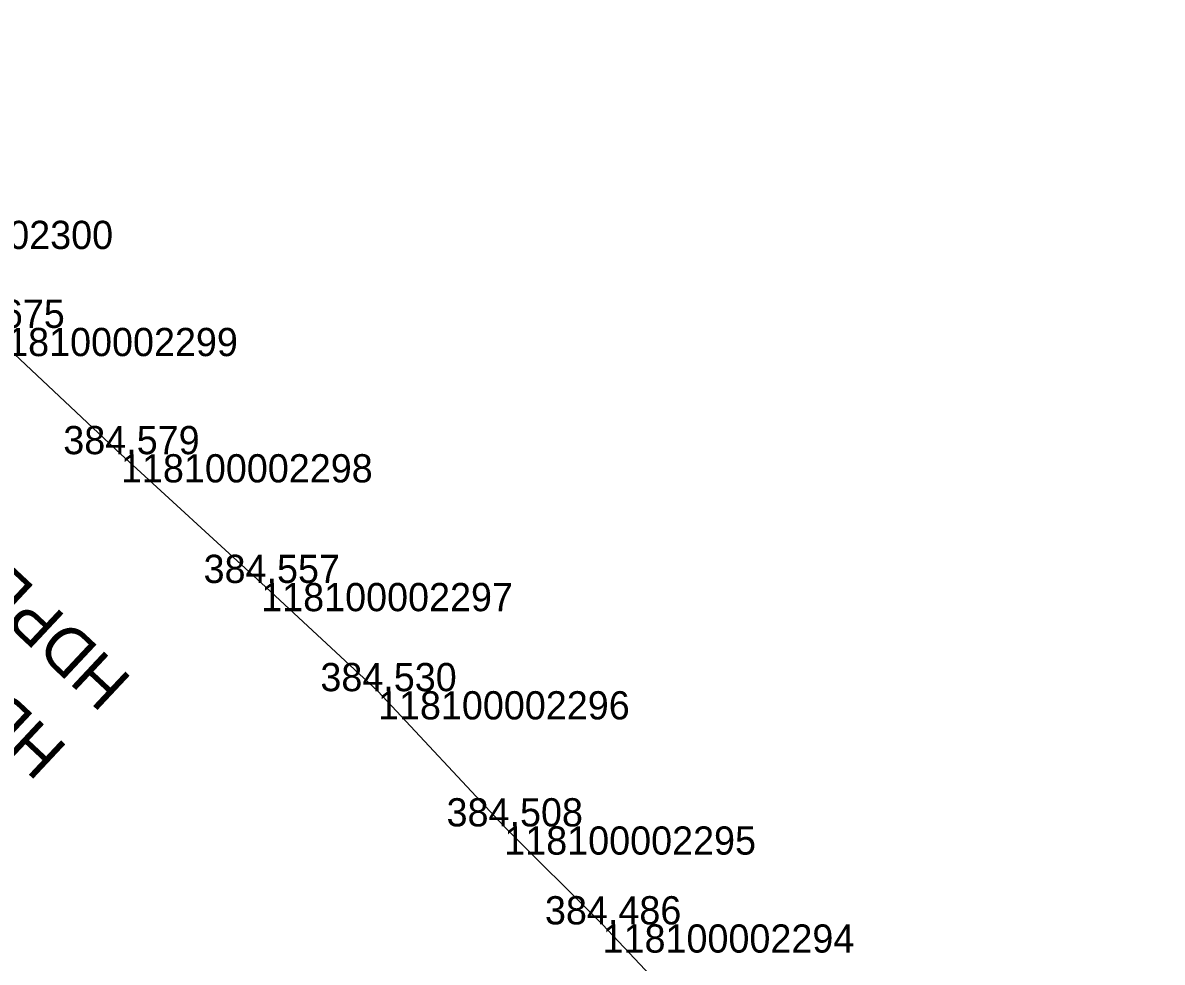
# Model space of a CAD drawing. Extents: x -724084 to -720954, y -948423 to -945131.
# Drawn here: x -721496.51 to -721448.03, y -947941.78 to -947901.83 of the extents above; entities that cross this region are included whole.
import ezdxf

# ---------------------------------------------------------------- set-up
doc = ezdxf.new("R2010")
doc.units = 0
for name, color, linetype in [('Vrstva 28', 7, 'Continuous'), ('Vrstva 31', 7, 'Continuous'), ('Vrstva 33', 7, 'Continuous'), ('Vrstva 60', 7, 'Continuous'), ('Vrstva 61', 7, 'Continuous')]:
    doc.layers.add(name, color=color, linetype=linetype)

msp = doc.modelspace()

# ---------------------------------------------------------------- linework, layer by layer
at = {"layer": 'Vrstva 28'}
msp.add_lwpolyline([(-721448.033, -947967.826), (-721449.454, -947966.459), (-721453.791, -947960.883), (-721457.946, -947955.954), (-721463.023, -947949.853), (-721466.622, -947945.714), (-721471.841, -947940.171), (-721476.024, -947936.004), (-721481.396, -947930.254), (-721486.364, -947925.652), (-721492.33, -947920.175), (-721498.065, -947914.804), (-721503.374, -947910.249), (-721507.766, -947906.168), (-721509.45, -947905.616), (-721512.086, -947903.222), (-721513.94, -947901.829)], dxfattribs=at)
at = {"layer": 'Vrstva 31'}
msp.add_lwpolyline([(-721448.033, -947967.826), (-721449.454, -947966.459), (-721453.791, -947960.883), (-721457.946, -947955.954), (-721463.023, -947949.853), (-721466.622, -947945.714), (-721471.841, -947940.171), (-721476.024, -947936.004), (-721481.396, -947930.254), (-721486.364, -947925.652), (-721492.33, -947920.175), (-721498.065, -947914.804), (-721503.374, -947910.249), (-721507.766, -947906.168), (-721509.45, -947905.616), (-721512.086, -947903.222), (-721513.94, -947901.829)], dxfattribs=at)
at = {"layer": 'Vrstva 33'}
msp.add_lwpolyline([(-721466.622, -947945.714), (-721471.841, -947940.171), (-721476.024, -947936.004), (-721481.396, -947930.254), (-721486.364, -947925.652), (-721492.33, -947920.175), (-721498.065, -947914.804)], dxfattribs=at)
at = {"layer": 'Vrstva 60'}
for p, q in [((-721492.33, -947920.175), (-721492.33, -947920.175)), ((-721486.364, -947925.652), (-721486.364, -947925.652)), ((-721481.396, -947930.254), (-721481.396, -947930.254)), ((-721476.024, -947936.004), (-721476.024, -947936.004)), ((-721471.841, -947940.171), (-721471.841, -947940.171))]:
    msp.add_line(p, q, dxfattribs=at)

# ---------------------------------------------------------------- texts
at = {"layer": 'Vrstva 33'}
for s, p in [('HDPE-černá', (-721491.803, -947929.743)), ('HDPE-modrá', (-721494.538, -947932.663))]:
    msp.add_text(s, height=2, rotation=136.8772, dxfattribs=at).set_placement(p)
at = {"layer": 'Vrstva 60'}
for s, p in [('118100002300', (-721503.374, -947911.449)), ('118100002299', (-721498.065, -947916.004)), ('118100002298', (-721492.33, -947921.375)), ('118100002297', (-721486.364, -947926.852)), ('118100002296', (-721481.396, -947931.454)), ('118100002295', (-721476.024, -947937.204)), ('118100002294', (-721471.841, -947941.371))]:
    msp.add_text(s, height=1.2, dxfattribs=at).set_placement(p)
at = {"layer": 'Vrstva 61'}
for s, p in [('384.675', (-721500.521, -947914.804)), ('384.579', (-721494.784, -947920.175)), ('384.557', (-721488.816, -947925.652)), ('384.530', (-721483.847, -947930.254)), ('384.508', (-721478.478, -947936.004)), ('384.486', (-721474.293, -947940.171))]:
    msp.add_text(s, height=1.2, dxfattribs=at).set_placement(p)

doc.saveas('drawing.dxf')
